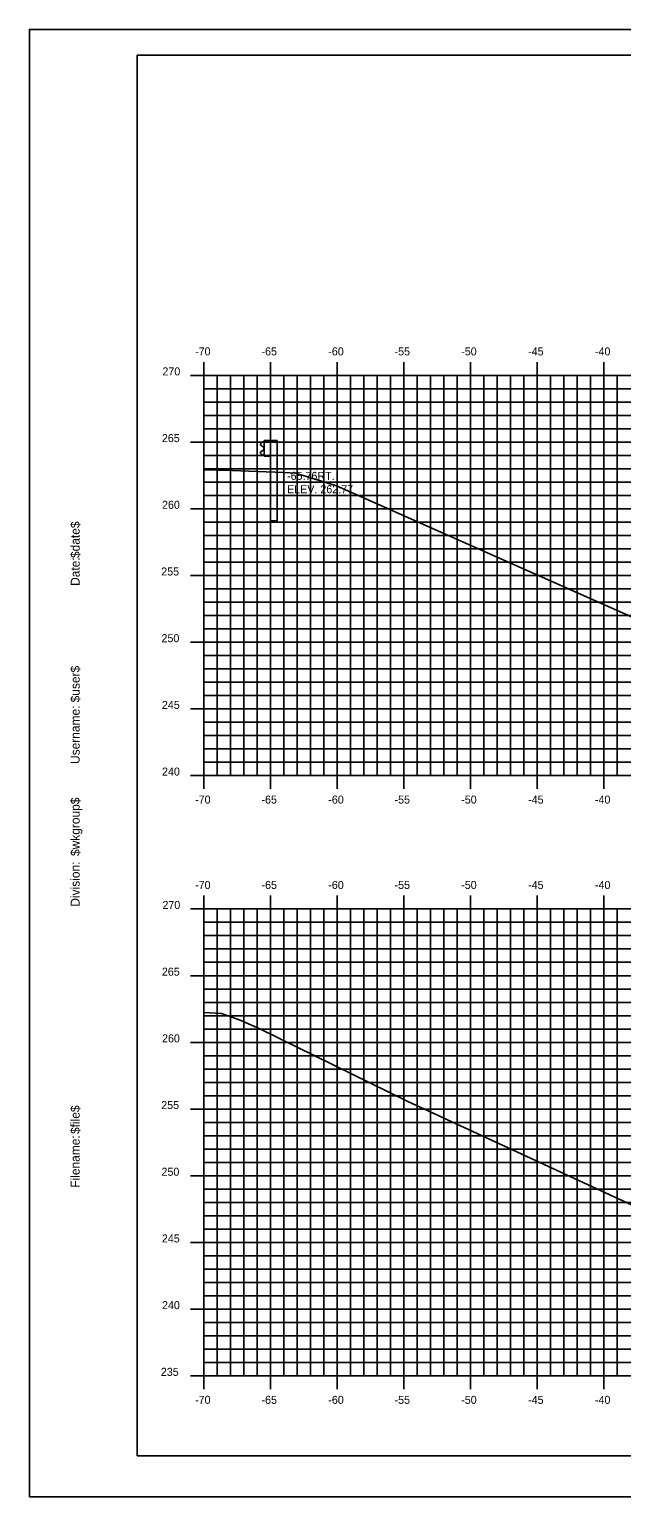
# Model space of a CAD drawing. Extents: x 1170543 to 1177585, y 609599 to 610623.
# Drawn here: x 1175274 to 1175318.4, y 609598.8 to 609708.8 of the extents above; entities that cross this region are included whole.
import ezdxf

# ---------------------------------------------------------------- set-up
doc = ezdxf.new("R2010")
doc.units = 0
for name, color, linetype in [('BORDER', 7, 'Continuous'), ('D_Text_Standard', 7, 'Continuous'), ('H_V ANNOTATION', 7, 'Continuous'), ('MAJOR', 7, 'Continuous'), ('MINOR', 7, 'Continuous'), ('PLOT BOUNDARY', 7, 'Continuous'), ('S_Guardrail_Beam', 7, 'Continuous'), ('S_Roadway_Centerline', 7, 'Continuous')]:
    doc.layers.add(name, color=color, linetype=linetype)

msp = doc.modelspace()

# ---------------------------------------------------------------- linework, layer by layer
at = {"layer": 'BORDER'}
for p, q in [((1175442.07, 609706.87), (1175282.07, 609706.87)), ((1175282.07, 609706.87), (1175282.07, 609601.87)), ((1175282.07, 609601.87), (1175442.07, 609601.87))]:
    msp.add_line(p, q, dxfattribs=at)
at = {"layer": 'MAJOR'}
for p, q in [((1175287.07, 609683.87), (1175287.07, 609682.87)), ((1175292.07, 609683.87), (1175292.07, 609682.87)), ((1175297.07, 609683.87), (1175297.07, 609682.87)), ((1175302.07, 609683.87), (1175302.07, 609682.87)), ((1175307.07, 609683.87), (1175307.07, 609682.87)), ((1175312.07, 609683.87), (1175312.07, 609682.87)), ((1175317.07, 609683.87), (1175317.07, 609682.87)), ((1175286.07, 609682.87), (1175287.07, 609682.87)), ((1175287.07, 609682.87), (1175427.07, 609682.87)), ((1175287.07, 609652.87), (1175287.07, 609682.87)), ((1175287.07, 609652.87), (1175287.07, 609682.87)), ((1175287.07, 609682.87), (1175427.07, 609682.87)), ((1175292.07, 609652.87), (1175292.07, 609682.87)), ((1175297.07, 609652.87), (1175297.07, 609682.87)), ((1175302.07, 609652.87), (1175302.07, 609682.87)), ((1175307.07, 609652.87), (1175307.07, 609682.87)), ((1175312.07, 609652.87), (1175312.07, 609682.87)), ((1175317.07, 609652.87), (1175317.07, 609682.87)), ((1175286.07, 609677.87), (1175287.07, 609677.87)), ((1175287.07, 609677.87), (1175427.07, 609677.87)), ((1175286.07, 609672.87), (1175287.07, 609672.87)), ((1175287.07, 609672.87), (1175427.07, 609672.87)), ((1175286.07, 609667.87), (1175287.07, 609667.87)), ((1175287.07, 609667.87), (1175427.07, 609667.87)), ((1175286.07, 609662.87), (1175287.07, 609662.87)), ((1175287.07, 609662.87), (1175427.07, 609662.87)), ((1175286.07, 609657.87), (1175287.07, 609657.87)), ((1175287.07, 609657.87), (1175427.07, 609657.87)), ((1175286.07, 609652.87), (1175287.07, 609652.87)), ((1175287.07, 609652.87), (1175427.07, 609652.87)), ((1175287.07, 609652.87), (1175427.07, 609652.87)), ((1175287.07, 609651.87), (1175287.07, 609652.87)), ((1175292.07, 609651.87), (1175292.07, 609652.87)), ((1175297.07, 609651.87), (1175297.07, 609652.87)), ((1175302.07, 609651.87), (1175302.07, 609652.87)), ((1175307.07, 609651.87), (1175307.07, 609652.87)), ((1175312.07, 609651.87), (1175312.07, 609652.87)), ((1175317.07, 609651.87), (1175317.07, 609652.87)), ((1175287.07, 609643.87), (1175287.07, 609642.87)), ((1175292.07, 609643.87), (1175292.07, 609642.87)), ((1175297.07, 609643.87), (1175297.07, 609642.87)), ((1175302.07, 609643.87), (1175302.07, 609642.87)), ((1175307.07, 609643.87), (1175307.07, 609642.87)), ((1175312.07, 609643.87), (1175312.07, 609642.87)), ((1175317.07, 609643.87), (1175317.07, 609642.87)), ((1175286.07, 609642.87), (1175287.07, 609642.87)), ((1175287.07, 609642.87), (1175427.07, 609642.87)), ((1175287.07, 609607.87), (1175287.07, 609642.87)), ((1175287.07, 609607.87), (1175287.07, 609642.87)), ((1175287.07, 609642.87), (1175427.07, 609642.87)), ((1175292.07, 609607.87), (1175292.07, 609642.87)), ((1175297.07, 609607.87), (1175297.07, 609642.87)), ((1175302.07, 609607.87), (1175302.07, 609642.87)), ((1175307.07, 609607.87), (1175307.07, 609642.87)), ((1175312.07, 609607.87), (1175312.07, 609642.87)), ((1175317.07, 609607.87), (1175317.07, 609642.87)), ((1175286.07, 609637.87), (1175287.07, 609637.87)), ((1175287.07, 609637.87), (1175427.07, 609637.87)), ((1175286.07, 609632.87), (1175287.07, 609632.87)), ((1175287.07, 609632.87), (1175427.07, 609632.87)), ((1175286.07, 609627.87), (1175287.07, 609627.87)), ((1175287.07, 609627.87), (1175427.07, 609627.87)), ((1175286.07, 609622.87), (1175287.07, 609622.87)), ((1175287.07, 609622.87), (1175427.07, 609622.87)), ((1175286.07, 609617.87), (1175287.07, 609617.87)), ((1175287.07, 609617.87), (1175427.07, 609617.87)), ((1175286.07, 609612.87), (1175287.07, 609612.87)), ((1175287.07, 609612.87), (1175427.07, 609612.87)), ((1175286.07, 609607.87), (1175287.07, 609607.87)), ((1175287.07, 609607.87), (1175427.07, 609607.87)), ((1175287.07, 609607.87), (1175427.07, 609607.87)), ((1175287.07, 609606.87), (1175287.07, 609607.87)), ((1175292.07, 609606.87), (1175292.07, 609607.87)), ((1175297.07, 609606.87), (1175297.07, 609607.87)), ((1175302.07, 609606.87), (1175302.07, 609607.87)), ((1175307.07, 609606.87), (1175307.07, 609607.87)), ((1175312.07, 609606.87), (1175312.07, 609607.87)), ((1175317.07, 609606.87), (1175317.07, 609607.87))]:
    msp.add_line(p, q, dxfattribs=at)
at = {"layer": 'MINOR'}
for p, q in [((1175288.07, 609652.87), (1175288.07, 609682.87)), ((1175289.07, 609652.87), (1175289.07, 609682.87)), ((1175290.07, 609652.87), (1175290.07, 609682.87)), ((1175291.07, 609652.87), (1175291.07, 609682.87)), ((1175293.07, 609652.87), (1175293.07, 609682.87)), ((1175294.07, 609652.87), (1175294.07, 609682.87)), ((1175295.07, 609652.87), (1175295.07, 609682.87)), ((1175296.07, 609652.87), (1175296.07, 609682.87)), ((1175298.07, 609652.87), (1175298.07, 609682.87)), ((1175299.07, 609652.87), (1175299.07, 609682.87)), ((1175300.07, 609652.87), (1175300.07, 609682.87)), ((1175301.07, 609652.87), (1175301.07, 609682.87)), ((1175303.07, 609652.87), (1175303.07, 609682.87)), ((1175304.07, 609652.87), (1175304.07, 609682.87)), ((1175305.07, 609652.87), (1175305.07, 609682.87)), ((1175306.07, 609652.87), (1175306.07, 609682.87)), ((1175308.07, 609652.87), (1175308.07, 609682.87)), ((1175309.07, 609652.87), (1175309.07, 609682.87)), ((1175310.07, 609652.87), (1175310.07, 609682.87)), ((1175311.07, 609652.87), (1175311.07, 609682.87)), ((1175313.07, 609652.87), (1175313.07, 609682.87)), ((1175314.07, 609652.87), (1175314.07, 609682.87)), ((1175315.07, 609652.87), (1175315.07, 609682.87)), ((1175316.07, 609652.87), (1175316.07, 609682.87)), ((1175318.07, 609652.87), (1175318.07, 609682.87)), ((1175287.07, 609681.87), (1175427.07, 609681.87)), ((1175287.07, 609681.87), (1175288.07, 609681.87)), ((1175287.07, 609680.87), (1175427.07, 609680.87)), ((1175287.07, 609680.87), (1175288.07, 609680.87)), ((1175287.07, 609679.87), (1175427.07, 609679.87)), ((1175287.07, 609679.87), (1175288.07, 609679.87)), ((1175287.07, 609678.87), (1175427.07, 609678.87)), ((1175287.07, 609678.87), (1175288.07, 609678.87)), ((1175287.07, 609676.87), (1175427.07, 609676.87)), ((1175287.07, 609676.87), (1175288.07, 609676.87)), ((1175287.07, 609675.87), (1175427.07, 609675.87)), ((1175287.07, 609675.87), (1175288.07, 609675.87)), ((1175287.07, 609674.87), (1175427.07, 609674.87)), ((1175287.07, 609674.87), (1175288.07, 609674.87)), ((1175287.07, 609673.87), (1175427.07, 609673.87)), ((1175287.07, 609673.87), (1175288.07, 609673.87)), ((1175287.07, 609671.87), (1175427.07, 609671.87)), ((1175287.07, 609671.87), (1175288.07, 609671.87)), ((1175287.07, 609670.87), (1175427.07, 609670.87)), ((1175287.07, 609670.87), (1175288.07, 609670.87)), ((1175287.07, 609669.87), (1175427.07, 609669.87)), ((1175287.07, 609669.87), (1175288.07, 609669.87)), ((1175287.07, 609668.87), (1175427.07, 609668.87)), ((1175287.07, 609668.87), (1175288.07, 609668.87)), ((1175287.07, 609666.87), (1175427.07, 609666.87)), ((1175287.07, 609666.87), (1175288.07, 609666.87)), ((1175287.07, 609665.87), (1175427.07, 609665.87)), ((1175287.07, 609665.87), (1175288.07, 609665.87)), ((1175287.07, 609664.87), (1175427.07, 609664.87)), ((1175287.07, 609664.87), (1175288.07, 609664.87)), ((1175287.07, 609663.87), (1175427.07, 609663.87)), ((1175287.07, 609663.87), (1175288.07, 609663.87)), ((1175287.07, 609661.87), (1175427.07, 609661.87)), ((1175287.07, 609661.87), (1175288.07, 609661.87)), ((1175287.07, 609660.87), (1175427.07, 609660.87)), ((1175287.07, 609660.87), (1175288.07, 609660.87)), ((1175287.07, 609659.87), (1175427.07, 609659.87)), ((1175287.07, 609659.87), (1175288.07, 609659.87)), ((1175287.07, 609658.87), (1175427.07, 609658.87)), ((1175287.07, 609658.87), (1175288.07, 609658.87)), ((1175287.07, 609656.87), (1175427.07, 609656.87)), ((1175287.07, 609656.87), (1175288.07, 609656.87)), ((1175287.07, 609655.87), (1175427.07, 609655.87)), ((1175287.07, 609655.87), (1175288.07, 609655.87)), ((1175287.07, 609654.87), (1175427.07, 609654.87)), ((1175287.07, 609654.87), (1175288.07, 609654.87)), ((1175287.07, 609653.87), (1175427.07, 609653.87)), ((1175287.07, 609653.87), (1175288.07, 609653.87)), ((1175288.07, 609607.87), (1175288.07, 609642.87)), ((1175289.07, 609607.87), (1175289.07, 609642.87)), ((1175290.07, 609607.87), (1175290.07, 609642.87)), ((1175291.07, 609607.87), (1175291.07, 609642.87)), ((1175293.07, 609607.87), (1175293.07, 609642.87)), ((1175294.07, 609607.87), (1175294.07, 609642.87)), ((1175295.07, 609607.87), (1175295.07, 609642.87)), ((1175296.07, 609607.87), (1175296.07, 609642.87)), ((1175298.07, 609607.87), (1175298.07, 609642.87)), ((1175299.07, 609607.87), (1175299.07, 609642.87)), ((1175300.07, 609607.87), (1175300.07, 609642.87)), ((1175301.07, 609607.87), (1175301.07, 609642.87)), ((1175303.07, 609607.87), (1175303.07, 609642.87)), ((1175304.07, 609607.87), (1175304.07, 609642.87)), ((1175305.07, 609607.87), (1175305.07, 609642.87)), ((1175306.07, 609607.87), (1175306.07, 609642.87)), ((1175308.07, 609607.87), (1175308.07, 609642.87)), ((1175309.07, 609607.87), (1175309.07, 609642.87)), ((1175310.07, 609607.87), (1175310.07, 609642.87)), ((1175311.07, 609607.87), (1175311.07, 609642.87)), ((1175313.07, 609607.87), (1175313.07, 609642.87)), ((1175314.07, 609607.87), (1175314.07, 609642.87)), ((1175315.07, 609607.87), (1175315.07, 609642.87)), ((1175316.07, 609607.87), (1175316.07, 609642.87)), ((1175318.07, 609607.87), (1175318.07, 609642.87)), ((1175287.07, 609641.87), (1175427.07, 609641.87)), ((1175287.07, 609641.87), (1175288.07, 609641.87)), ((1175287.07, 609640.87), (1175427.07, 609640.87)), ((1175287.07, 609640.87), (1175288.07, 609640.87)), ((1175287.07, 609639.87), (1175427.07, 609639.87)), ((1175287.07, 609639.87), (1175288.07, 609639.87)), ((1175287.07, 609638.87), (1175427.07, 609638.87)), ((1175287.07, 609638.87), (1175288.07, 609638.87)), ((1175287.07, 609636.87), (1175427.07, 609636.87)), ((1175287.07, 609636.87), (1175288.07, 609636.87)), ((1175287.07, 609635.87), (1175427.07, 609635.87)), ((1175287.07, 609635.87), (1175288.07, 609635.87)), ((1175287.07, 609634.87), (1175427.07, 609634.87)), ((1175287.07, 609634.87), (1175288.07, 609634.87)), ((1175287.07, 609633.87), (1175427.07, 609633.87)), ((1175287.07, 609633.87), (1175288.07, 609633.87)), ((1175287.07, 609631.87), (1175427.07, 609631.87)), ((1175287.07, 609631.87), (1175288.07, 609631.87)), ((1175287.07, 609630.87), (1175427.07, 609630.87)), ((1175287.07, 609630.87), (1175288.07, 609630.87)), ((1175287.07, 609629.87), (1175427.07, 609629.87)), ((1175287.07, 609629.87), (1175288.07, 609629.87)), ((1175287.07, 609628.87), (1175427.07, 609628.87)), ((1175287.07, 609628.87), (1175288.07, 609628.87)), ((1175287.07, 609626.87), (1175427.07, 609626.87)), ((1175287.07, 609626.87), (1175288.07, 609626.87)), ((1175287.07, 609625.87), (1175427.07, 609625.87)), ((1175287.07, 609625.87), (1175288.07, 609625.87)), ((1175287.07, 609624.87), (1175427.07, 609624.87)), ((1175287.07, 609624.87), (1175288.07, 609624.87)), ((1175287.07, 609623.87), (1175427.07, 609623.87)), ((1175287.07, 609623.87), (1175288.07, 609623.87)), ((1175287.07, 609621.87), (1175427.07, 609621.87)), ((1175287.07, 609621.87), (1175288.07, 609621.87)), ((1175287.07, 609620.87), (1175427.07, 609620.87)), ((1175287.07, 609620.87), (1175288.07, 609620.87)), ((1175287.07, 609619.87), (1175427.07, 609619.87)), ((1175287.07, 609619.87), (1175288.07, 609619.87)), ((1175287.07, 609618.87), (1175427.07, 609618.87)), ((1175287.07, 609618.87), (1175288.07, 609618.87)), ((1175287.07, 609616.87), (1175427.07, 609616.87)), ((1175287.07, 609616.87), (1175288.07, 609616.87)), ((1175287.07, 609615.87), (1175427.07, 609615.87)), ((1175287.07, 609615.87), (1175288.07, 609615.87)), ((1175287.07, 609614.87), (1175427.07, 609614.87)), ((1175287.07, 609614.87), (1175288.07, 609614.87)), ((1175287.07, 609613.87), (1175427.07, 609613.87)), ((1175287.07, 609613.87), (1175288.07, 609613.87)), ((1175287.07, 609611.87), (1175427.07, 609611.87)), ((1175287.07, 609611.87), (1175288.07, 609611.87)), ((1175287.07, 609610.87), (1175427.07, 609610.87)), ((1175287.07, 609610.87), (1175288.07, 609610.87)), ((1175287.07, 609609.87), (1175427.07, 609609.87)), ((1175287.07, 609609.87), (1175288.07, 609609.87)), ((1175287.07, 609608.87), (1175427.07, 609608.87)), ((1175287.07, 609608.87), (1175288.07, 609608.87))]:
    msp.add_line(p, q, dxfattribs=at)
at = {"layer": 'PLOT BOUNDARY'}
msp.add_lwpolyline([(1175273.98, 609598.81), (1175443.98, 609598.81), (1175443.98, 609708.81), (1175273.98, 609708.81)], close=True, dxfattribs=at)
at = {"layer": 'S_Guardrail_Beam'}
for p, q in [((1175291.48, 609677.88), (1175291.34, 609677.78)), ((1175291.34, 609677.64), (1175291.53, 609677.5)), ((1175291.53, 609677.28), (1175291.34, 609677.15)), ((1175291.58, 609677.9), (1175291.5, 609677.89)), ((1175291.57, 609677.44), (1175291.57, 609677.35)), ((1175291.58, 609677.98), (1175292.07, 609677.98)), ((1175291.58, 609676.81), (1175291.58, 609677.98)), ((1175292.07, 609677.98), (1175292.56, 609677.98)), ((1175292.07, 609677.98), (1175292.07, 609676.81)), ((1175292.56, 609677.98), (1175292.56, 609671.98)), ((1175291.34, 609677), (1175291.48, 609676.9)), ((1175291.5, 609676.9), (1175291.58, 609676.88)), ((1175292.07, 609676.81), (1175291.58, 609676.81)), ((1175292.07, 609671.98), (1175292.07, 609676.81)), ((1175292.07, 609671.98), (1175292.56, 609671.98))]:
    msp.add_line(p, q, dxfattribs=at)
for centre, major_axis, start_param, end_param in [((1175291.39, 609677.71), (-0.0877, 0), 5.323254, 7.243116), ((1175291.51, 609677.85), (-0.0417, 0), 4.886922, 5.323254), ((1175291.49, 609677.44), (0.0789, 0), 0, 0.959931), ((1175291.49, 609677.35), (0.0789, 0), 5.323254, 6.283185), ((1175291.39, 609677.08), (-0.0877, 0), 5.323254, 7.243116), ((1175291.51, 609676.94), (-0.0417, 0), 0.959931, 1.396263)]:
    msp.add_ellipse(centre, major_axis=major_axis, ratio=0.995501, start_param=start_param, end_param=end_param, dxfattribs=at)
at = {"layer": 'S_Roadway_Centerline'}
for points in [[(1175287.07, 609675.79), (1175289.21, 609675.74), (1175291.07, 609675.66), (1175293.1, 609675.58), (1175293.99, 609675.54), (1175294.11, 609675.5), (1175297.01, 609674.58), (1175320.28, 609664.27)], [(1175287.07, 609635.1), (1175288.38, 609635.04), (1175288.88, 609634.87), (1175289.78, 609634.54), (1175291.27, 609633.89), (1175302.31, 609628.45), (1175328.76, 609616.23)]]:
    msp.add_lwpolyline(points, dxfattribs=at)

# ---------------------------------------------------------------- texts
at = {"layer": 'BORDER'}
for s, p in [('$date$', (1175277.75, 609669.18)), ('Date:', (1175277.75, 609667.09)), ('$user$', (1175277.75, 609658.36)), ('Username:', (1175277.75, 609653.74)), ('$wkgroup$', (1175277.75, 609646.84)), ('Division:', (1175277.75, 609643.04)), ('$file$', (1175277.75, 609626)), ('Filename:', (1175277.75, 609621.97))]:
    msp.add_text(s, height=0.67, rotation=90, dxfattribs=at).set_placement(p)
at = {"layer": 'D_Text_Standard'}
for s, p in [('-65.76RT.', (1175293.31, 609675.04)), ('ELEV. 262.77', (1175293.31, 609674.04))]:
    msp.add_text(s, height=0.6, dxfattribs=at).set_placement(p)
at = {"layer": 'H_V ANNOTATION'}
for s, p in [('-70', (1175286.41, 609684.37)), ('-65', (1175291.39, 609684.37)), ('-60', (1175296.4, 609684.37)), ('-55', (1175301.37, 609684.37)), ('-50', (1175306.37, 609684.37)), ('-45', (1175311.39, 609684.37)), ('-40', (1175316.4, 609684.37)), ('270', (1175283.96, 609682.87)), ('265', (1175283.92, 609677.87)), ('260', (1175283.93, 609672.87)), ('255', (1175283.87, 609667.87)), ('250', (1175283.89, 609662.87)), ('245', (1175283.92, 609657.87)), ('240', (1175283.93, 609652.87)), ('-70', (1175286.41, 609650.77)), ('-65', (1175291.39, 609650.77)), ('-60', (1175296.4, 609650.77)), ('-55', (1175301.37, 609650.77)), ('-50', (1175306.37, 609650.77)), ('-45', (1175311.39, 609650.77)), ('-40', (1175316.4, 609650.77)), ('-70', (1175286.41, 609644.37)), ('-65', (1175291.39, 609644.37)), ('-60', (1175296.4, 609644.37)), ('-55', (1175301.37, 609644.37)), ('-50', (1175306.37, 609644.37)), ('-45', (1175311.39, 609644.37)), ('-40', (1175316.4, 609644.37)), ('270', (1175283.96, 609642.87)), ('265', (1175283.92, 609637.87)), ('260', (1175283.93, 609632.87)), ('255', (1175283.87, 609627.87)), ('250', (1175283.89, 609622.87)), ('245', (1175283.92, 609617.87)), ('240', (1175283.93, 609612.87)), ('235', (1175283.84, 609607.87)), ('-70', (1175286.41, 609605.77)), ('-65', (1175291.39, 609605.77)), ('-60', (1175296.4, 609605.77)), ('-55', (1175301.37, 609605.77)), ('-50', (1175306.37, 609605.77)), ('-45', (1175311.39, 609605.77)), ('-40', (1175316.4, 609605.77))]:
    msp.add_text(s, height=0.6, dxfattribs=at).set_placement(p)

doc.saveas('drawing.dxf')
